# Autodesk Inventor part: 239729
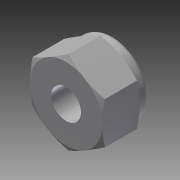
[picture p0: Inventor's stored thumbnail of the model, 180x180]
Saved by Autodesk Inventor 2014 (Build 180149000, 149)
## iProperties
Shininess: 20.0
Length Units: 11272
Angle Units: 11279
Time Units: 11290
Mass Units: 11286
Length Display Precision: 3
Angle Display Precision: 2
Company: Autodesk, Inc.
Created: 2001-10
Part Number: 239729
Material: Stainless Steel, 440C
Description: Lock-nut; #10~32 (SS)
Document SubType Name: Modeling
Designer: Autodesk, Inc.
Density: 8.94 g/cm^3
Appearance: Steel
Density: 8.94
Volumn: 1.3062604850048036
Area: 10.612586411503024
PropertySet Name: Model Information
Control State: 0
Master: False
Checked Out: False
Last Check In By: JT
Last Check In Date: 2003-06-20
MODEL - 1: ---
MODEL - 2: ---
RAW MATERIAL: --------
SCALE:: 1=??
SIZE: 00 x 00 x 00
SUB-ASSY - 1: ------
SUB-ASSY - 1 - QUA: 1
SUB-ASSY - 2: ------
SUB-ASSY - 2 - QUA: 1
SYM. TO:: N/A
TEMPLATE CREATION: -- / __-__-__
Author: Autodesk, Inc.
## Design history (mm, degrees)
sketch "Sketch1"
  geometry: L1 (0, -5.334)-(-4.619, -2.667); L2 (-4.619, -2.667)-(-4.619, 2.667); L3 (-4.619, 2.667)-(0, 5.334); L4 (0, 5.334)-(4.619, 2.667); L5 (4.619, 2.667)-(4.619, -2.667); L6 (4.619, -2.667)-(0, -5.334); C1 r 1.899 at (0, 0); 2 further points
  constraints: 12 end point, 2 coincident, 1 centre point, 11 other
  dimensions: "Corners" = 10.668 distance of L3.end L1.start; "Ins_Thd_Dia" = 3.7973 diameter of C1
extrude "Extrusion2" new body sketch "Sketch1" taper "d6" = 0 deg; distance "Hex_Thk" = 4.7498
sketch "Sketch2"
  geometry: L1 (0, -5.334)-(4.619, -2.667) reference; C1 r 1.899 at (0, 0) reference; C2 r 4.619 at (0, 0)
  constraints: 1 centre point, 1 coincident, 1 tangent
  dimensions: "Corner_Cut" = 9.23876 diameter of C2 (derived)
extrude "Extrusion3" join sketch "Sketch2" taper "d8" = 0 deg; distance "Overall_Thk" = 1.3462 (computed from Hex_Thk)
fillet "Fillet1" dims "Radius" = 0.6731 (= 0.5 x Overall_Thk)
sketch "Sketch3"
  geometry: L1 (-5.334, 0)-(-5.334, 0.333); L2 (-5.334, 4.417)-(-5.334, 4.75); L3 (0, 0)-(0, 6.426); L4 (-5.334, 0)-(-4.619, 0); L5 (-5.334, 0.333)-(-4.619, 0); L6 (-5.334, 4.75)-(-4.619, 4.75); L7 (-4.619, 4.75)-(-5.334, 4.417); L8 (-4.619, 0)-(-4.619, 4.75)
  constraints: 16 end point, 3 parallel, 1 collinear, 1 perpendicular
  dimensions: "d17" = 25 deg angle of L5 L4; "d18" = 25 deg angle of L7 L6; "d19" = 9.23876 diameter of L8 L3 (= Corner_Cut)
revolve "Revolution1" sketch "Sketch3" stored, may be unused: angle "d13" = 90 deg
fillet "Fillet2" dims "d21" = 0.381 (= Top_Rad)
workplane "Work Plane1"
sketch "Sketch4"
  geometry: C1 r 1.899 at (0, 0) reference; C2 r 1.518 at (0, 0); 1 further point
  constraints: 1 centre point, 1 coincident
  dimensions: "d23" = 0.381 radial gap between concentric circles of C2 C1 (= Nylon_Width)
extrude "Extrusion4" join sketch "Sketch4" distance "d24" = 0.381 (= Nylon_Depth); taper "d25" = 0 deg
thread "Thread1" dims "d14" = 25.4, "d15" = 0
body "Solid1"
other parameters: "Top_Rad" = 0.381 [user parameter; used in 2 equation terms], "d22" = -0.381 (= -Top_Rad), "Nylon_Width" = 0.381 [user parameter; used in 1 equation term], "Nylon_Depth" = 0.381 [user parameter; used in 1 equation term]
